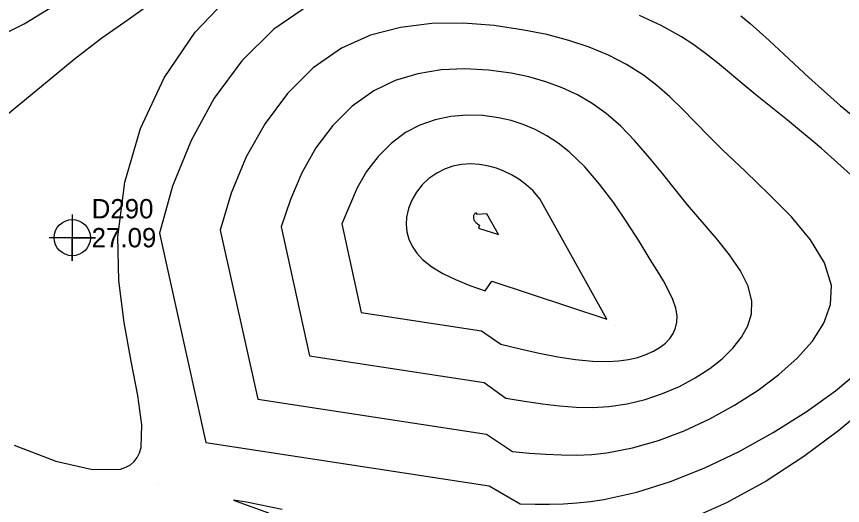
# Model space of a CAD drawing. Extents: x 2356077 to 2359823, y 225951 to 227822.
# Drawn here: x 2356347.8 to 2356454.6, y 227296.2 to 227359.5 of the extents above; entities that cross this region are included whole.
import ezdxf

# ---------------------------------------------------------------- set-up
doc = ezdxf.new("R2010")
doc.units = 0
for name, color, linetype in [('DTM Contours Major', 7, 'Continuous'), ('DTM Contours Minor', 7, 'Continuous'), ('Exist DTM Regular Point CELL', 7, 'Continuous'), ('Exist DTM Regular Point Cogo Elevation', 7, 'Continuous'), ('Exist DTM Regular Point Cogo Number', 7, 'Continuous'), ('PH Exist DTM Point', 7, 'Continuous')]:
    doc.layers.add(name, color=color, linetype=linetype)

msp = doc.modelspace()

# ---------------------------------------------------------------- linework, layer by layer
at = {"layer": 'DTM Contours Major'}
for points in [[(2356347.66, 227422.41), (2356348.48, 227421.09), (2356352.86, 227414.5), (2356358.25, 227406.51), (2356363.81, 227397.77), (2356368.74, 227388.92), (2356372.2, 227380.58), (2356373.38, 227373.4), (2356372.67, 227369.75), (2356370.99, 227366.65), (2356368.55, 227363.94), (2356365.57, 227361.48), (2356362.26, 227359.11), (2356358.84, 227356.7), (2356355.24, 227353.94), (2356351.75, 227351.08), (2356348.37, 227348.25), (2356345.1, 227345.58)], [(2356347.48, 227304.05), (2356352.87, 227301.95), (2356357.62, 227300.86), (2356361.24, 227300.94), (2356361.94, 227301.17), (2356362.53, 227301.5), (2356363.02, 227301.92), (2356363.41, 227302.44), (2356363.71, 227303.04), (2356363.91, 227303.74), (2356364.03, 227306.66), (2356363.51, 227310.44), (2356362.64, 227314.91), (2356361.72, 227319.93), (2356361.05, 227325.35), (2356360.92, 227331.01), (2356361.81, 227338.07), (2356363.84, 227345.02), (2356366.91, 227351.58), (2356370.89, 227357.51), (2356375.69, 227362.54)], [(2356441.47, 227359.61), (2356442.68, 227358.6), (2356443.9, 227357.54), (2356445.14, 227356.41), (2356446.42, 227355.22), (2356450.24, 227351.64), (2356454.3, 227347.98), (2356458.36, 227344.66)], [(2356424.12, 227320.35), (2356415.49, 227335.93), (2356414.56, 227337.01), (2356413.66, 227337.78), (2356412.74, 227338.46), (2356411.8, 227339.03), (2356410.84, 227339.51), (2356409.87, 227339.88), (2356408.89, 227340.16), (2356407.69, 227340.37), (2356406.5, 227340.44), (2356405.34, 227340.35), (2356404.21, 227340.13), (2356403.14, 227339.77), (2356402.14, 227339.26), (2356401.14, 227338.56), (2356400.26, 227337.73), (2356399.51, 227336.78), (2356398.92, 227335.76), (2356398.48, 227334.67), (2356398.24, 227333.56), (2356398.18, 227332.59), (2356398.28, 227331.63), (2356398.54, 227330.68), (2356398.96, 227329.77), (2356399.55, 227328.9), (2356400.3, 227328.08), (2356401.5, 227327.13), (2356402.94, 227326.26), (2356404.59, 227325.46), (2356406.43, 227324.71), (2356408.42, 227323.99), (2356409.29, 227325.24), (2356424.12, 227320.35)], [(2356457.51, 227308.73), (2356454.12, 227305.95), (2356449.6, 227302.57), (2356444.75, 227299.39), (2356439.6, 227296.55), (2356434.2, 227294.16)], [(2356382.14, 227295.71), (2356377.56, 227296.66), (2356375.87, 227296.92), (2356377.15, 227296.42), (2356380.37, 227295.28)]]:
    msp.add_lwpolyline(points, dxfattribs=at)
at = {"layer": 'DTM Contours Minor'}
for points in [[(2356341.2, 227354.76), (2356348.78, 227358.59), (2356355.9, 227362.97), (2356361.63, 227368.06), (2356366.11, 227373.66), (2356365.39, 227381.1), (2356363.12, 227388.84), (2356358.95, 227396.8), (2356353.97, 227404.59), (2356348.71, 227411.76), (2356344.08, 227417.88)], [(2356385.67, 227361.02), (2356381.07, 227357.88), (2356376.96, 227353.79), (2356373.38, 227348.93), (2356370.37, 227343.46), (2356367.97, 227337.56), (2356366.31, 227331.47), (2356372.29, 227304.38)], [(2356456.07, 227338.69), (2356451.86, 227342.49), (2356447.5, 227346.08), (2356443.41, 227349.38), (2356441.65, 227350.85), (2356440, 227352.23), (2356438.43, 227353.52), (2356436.9, 227354.73), (2356435.37, 227355.86), (2356433.79, 227356.9), (2356431.18, 227358.37), (2356428.36, 227359.65)], [(2356378.99, 227309.99), (2356408.59, 227305.46), (2356411.94, 227303.22), (2356414.15, 227303.01), (2356416.25, 227302.85), (2356418.27, 227302.76), (2356420.25, 227302.75), (2356422.2, 227302.84), (2356424.16, 227303.05), (2356427.46, 227303.68), (2356430.8, 227304.64), (2356434.15, 227305.9), (2356437.45, 227307.43), (2356440.66, 227309.2), (2356443.72, 227311.17), (2356446.37, 227313.16), (2356448.74, 227315.28), (2356450.72, 227317.51), (2356452.2, 227319.83), (2356453.05, 227322.23), (2356453.18, 227324.69), (2356452.29, 227327.64), (2356450.49, 227330.62), (2356448.01, 227333.59), (2356445.11, 227336.54), (2356442.06, 227339.44), (2356439.09, 227342.26), (2356437.27, 227344.08), (2356435.56, 227345.85), (2356433.91, 227347.53), (2356432.27, 227349.11), (2356430.61, 227350.59), (2356428.88, 227351.93), (2356426.7, 227353.32), (2356424.37, 227354.52), (2356421.87, 227355.56), (2356419.21, 227356.43), (2356416.39, 227357.17), (2356413.41, 227357.77), (2356409.55, 227358.34), (2356405.55, 227358.65), (2356401.49, 227358.6), (2356397.47, 227358.11), (2356393.56, 227357.09), (2356389.85, 227355.44), (2356386.15, 227352.86), (2356382.83, 227349.57), (2356379.94, 227345.68), (2356377.51, 227341.34), (2356375.58, 227336.67), (2356374.16, 227331.88), (2356378.99, 227309.99)], [(2356385.69, 227315.59), (2356408.26, 227312.14), (2356411.08, 227310.12), (2356413.49, 227309.72), (2356415.8, 227309.38), (2356418.02, 227309.11), (2356420.18, 227308.95), (2356422.3, 227308.92), (2356424.38, 227309.03), (2356426.76, 227309.38), (2356429.09, 227309.94), (2356431.36, 227310.7), (2356433.52, 227311.64), (2356435.57, 227312.74), (2356437.46, 227313.97), (2356439.05, 227315.22), (2356440.43, 227316.57), (2356441.56, 227317.99), (2356442.39, 227319.49), (2356442.85, 227321.05), (2356442.91, 227322.65), (2356442.43, 227324.6), (2356441.42, 227326.6), (2356440.01, 227328.66), (2356438.32, 227330.77), (2356434.58, 227335.15), (2356432.85, 227337.28), (2356431.15, 227339.41), (2356429.45, 227341.49), (2356427.72, 227343.48), (2356425.93, 227345.33), (2356424.04, 227346.98), (2356422.25, 227348.27), (2356420.35, 227349.37), (2356418.35, 227350.3), (2356416.25, 227351.07), (2356414.05, 227351.69), (2356411.76, 227352.17), (2356408.82, 227352.58), (2356405.79, 227352.74), (2356402.73, 227352.6), (2356399.71, 227352.12), (2356396.78, 227351.24), (2356394.01, 227349.91), (2356391.22, 227347.91), (2356388.71, 227345.41), (2356386.52, 227342.5), (2356384.69, 227339.28), (2356383.24, 227335.83), (2356382.01, 227332.28), (2356385.69, 227315.59)], [(2356392.39, 227321.2), (2356407.92, 227318.82), (2356410.45, 227317.11), (2356412.95, 227316.5), (2356415.41, 227315.95), (2356417.8, 227315.47), (2356420.09, 227315.12), (2356422.27, 227314.9), (2356424.32, 227314.86), (2356425.67, 227314.95), (2356426.95, 227315.13), (2356428.13, 227315.4), (2356429.2, 227315.76), (2356430.17, 227316.2), (2356431.03, 227316.71), (2356431.71, 227317.25), (2356432.28, 227317.84), (2356432.73, 227318.49), (2356433.04, 227319.2), (2356433.21, 227319.95), (2356433.23, 227320.76), (2356433.05, 227321.78), (2356432.68, 227322.87), (2356432.13, 227324.04), (2356431.45, 227325.3), (2356430.65, 227326.64), (2356429.76, 227328.07), (2356428.31, 227330.42), (2356426.73, 227332.89), (2356425.03, 227335.38), (2356423.21, 227337.8), (2356421.28, 227340.05), (2356419.25, 227342.02), (2356417.83, 227343.13), (2356416.38, 227344.09), (2356414.88, 227344.89), (2356413.34, 227345.54), (2356411.75, 227346.05), (2356410.13, 227346.42), (2356408.09, 227346.69), (2356406.02, 227346.75), (2356403.95, 227346.58), (2356401.92, 227346.16), (2356399.96, 227345.47), (2356398.11, 227344.5), (2356396.24, 227343.1), (2356394.55, 227341.41), (2356393.08, 227339.47), (2356391.85, 227337.34), (2356389.86, 227332.69), (2356392.39, 227321.2)], [(2356410.12, 227331.3), (2356408.63, 227333.99), (2356407.28, 227333.91), (2356407.31, 227333.95), (2356407.32, 227333.99), (2356407.33, 227334.02), (2356407.33, 227334.04), (2356407.31, 227334.06), (2356407.29, 227334.07), (2356407.26, 227334.08), (2356407.22, 227334.07), (2356407.18, 227334.06), (2356407.13, 227334.03), (2356407.08, 227334), (2356407.03, 227333.95), (2356406.99, 227333.89), (2356406.95, 227333.82), (2356406.91, 227333.74), (2356406.89, 227333.65), (2356406.88, 227333.56), (2356406.88, 227333.46), (2356406.89, 227333.38), (2356406.92, 227333.29), (2356406.95, 227333.2), (2356407, 227333.11), (2356407.05, 227333.03), (2356407.11, 227332.94), (2356407.21, 227332.85), (2356407.31, 227332.75), (2356407.42, 227332.67), (2356407.54, 227332.59), (2356407.66, 227332.53), (2356407.55, 227332.14), (2356410.12, 227331.3)], [(2356372.29, 227304.38), (2356408.92, 227298.77), (2356412.95, 227296.42), (2356414.89, 227296.38), (2356416.74, 227296.38), (2356418.53, 227296.44), (2356420.28, 227296.55), (2356422.02, 227296.74), (2356423.77, 227297), (2356428.02, 227297.94), (2356432.39, 227299.32), (2356436.83, 227301.09), (2356441.27, 227303.22), (2356445.65, 227305.65), (2356449.92, 227308.35), (2356453.7, 227311.06), (2356457.14, 227313.94)]]:
    msp.add_lwpolyline(points, dxfattribs=at)
at = {"layer": 'Exist DTM Regular Point CELL'}
msp.add_lwpolyline([(2356355.02, 227333.89), (2356355.02, 227327.89), (2356355.02, 227330.89), (2356358.02, 227330.89), (2356352.02, 227330.89)], dxfattribs=at)
msp.add_circle((2356355.02, 227330.89), 2.34, dxfattribs=at)
at = {"layer": 'PH Exist DTM Point'}
for p, q in [((2356407.19, 227333.58), (2356407.19, 227333.58)), ((2356425.26, 227319.47), (2356425.26, 227319.47)), ((2356365.98, 227299.09), (2356365.98, 227299.09))]:
    msp.add_line(p, q, dxfattribs=at)

# ---------------------------------------------------------------- texts
at = {"layer": 'Exist DTM Regular Point Cogo Elevation'}
msp.add_text('27.09', height=2.5, dxfattribs=at).set_placement((2356357.52, 227329.64))
at = {"layer": 'Exist DTM Regular Point Cogo Number'}
msp.add_text('D290', height=2.5, dxfattribs=at).set_placement((2356357.52, 227333.39))

doc.saveas('drawing.dxf')
